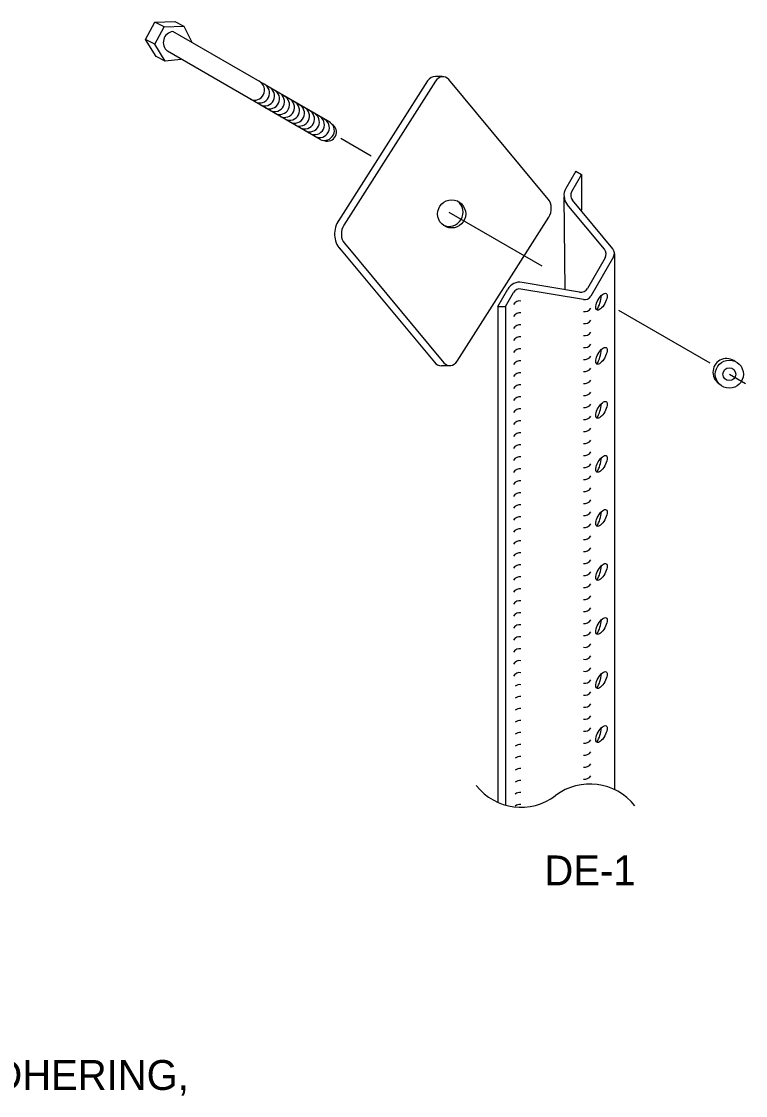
# Model space of a CAD drawing. Extents: x -0.14 to 2.7, y -0.05 to 1.78.
# Drawn here: x 0.3019 to 0.5037, y 1.2916 to 1.5909 of the extents above; entities that cross this region are included whole.
import ezdxf

# ---------------------------------------------------------------- set-up
doc = ezdxf.new("R2010")
doc.units = 0
doc.layers.add('CT_CSHT_GeneralLabel', color=7, linetype='Continuous')

msp = doc.modelspace()

# ---------------------------------------------------------------- linework, layer by layer
at = {"layer": 'CT_CSHT_GeneralLabel'}
for p, q in [((0.3364926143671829, 1.585867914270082), (0.3390890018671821, 1.590740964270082)), ((0.3390890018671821, 1.590740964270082), (0.34461068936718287, 1.590921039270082)), ((0.3416651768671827, 1.5894363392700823), (0.3390890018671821, 1.590740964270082)), ((0.34461068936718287, 1.590921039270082), (0.3471850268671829, 1.5896164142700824)), ((0.38788748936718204, 1.5628238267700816), (0.34410170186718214, 1.5881115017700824)), ((0.33940321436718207, 1.581174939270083), (0.3364926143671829, 1.585867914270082)), ((0.33906327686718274, 1.5845632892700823), (0.3364926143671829, 1.585867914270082)), ((0.34197755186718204, 1.5798721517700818), (0.33940321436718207, 1.581174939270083)), ((0.3851294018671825, 1.5580481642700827), (0.3425655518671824, 1.582633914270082)), ((0.4191782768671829, 1.575577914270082), (0.4173242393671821, 1.5756091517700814)), ((0.44870873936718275, 1.5414187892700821), (0.42096616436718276, 1.5747198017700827)), ((0.415060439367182, 1.574332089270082), (0.39022662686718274, 1.5353642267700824)), ((0.4172801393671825, 1.5742530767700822), (0.3917425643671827, 1.534177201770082)), ((0.3909303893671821, 1.5584028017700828), (0.3993975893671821, 1.5535150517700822)), ((0.4563747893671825, 1.549162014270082), (0.4536056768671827, 1.5443624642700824)), ((0.45799730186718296, 1.5482267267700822), (0.4552281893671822, 1.5434253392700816)), ((0.4563747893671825, 1.549162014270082), (0.45799730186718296, 1.5482267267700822)), ((0.45799730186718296, 1.5482267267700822), (0.45799730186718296, 1.5383464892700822)), ((0.4534347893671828, 1.5161568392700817), (0.4531095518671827, 1.542030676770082)), ((0.4643440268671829, 1.5274427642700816), (0.45397685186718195, 1.5399506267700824)), ((0.46667765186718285, 1.527565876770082), (0.45542112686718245, 1.5411468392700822)), ((0.4210378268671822, 1.5377327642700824), (0.4468932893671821, 1.5227994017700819)), ((0.4233291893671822, 1.4962732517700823), (0.448863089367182, 1.5363491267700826)), ((0.3905224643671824, 1.5276926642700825), (0.4169787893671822, 1.4959425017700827)), ((0.3918969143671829, 1.5291020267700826), (0.419646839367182, 1.495806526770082)), ((0.4645498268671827, 1.525013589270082), (0.45964370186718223, 1.5165114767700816)), ((0.4668687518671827, 1.5252818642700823), (0.4605679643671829, 1.5143652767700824)), ((0.4671351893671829, 1.5261712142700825), (0.4671351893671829, 1.3768578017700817)), ((0.4574350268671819, 1.515476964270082), (0.4414175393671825, 1.518198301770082)), ((0.434635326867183, 1.5115208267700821), (0.4374026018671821, 1.5163075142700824)), ((0.43680541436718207, 1.5115208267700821), (0.4390324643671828, 1.5153777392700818)), ((0.4584971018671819, 1.5133950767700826), (0.44110516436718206, 1.516351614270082)), ((0.434635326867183, 1.5115208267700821), (0.43680541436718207, 1.5115208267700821)), ((0.434635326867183, 1.5115208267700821), (0.434635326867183, 1.3733004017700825)), ((0.43680541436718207, 1.5115208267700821), (0.43680541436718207, 1.3725139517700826)), ((0.49380466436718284, 1.495712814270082), (0.46839387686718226, 1.5103870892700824)), ((0.4212601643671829, 1.4949429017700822), (0.4189173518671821, 1.4949833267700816)), ((0.49918302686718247, 1.4926092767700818), (0.5036812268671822, 1.4900110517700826))]:
    msp.add_line(p, q, dxfattribs=at)
msp.add_lwpolyline([(0.34627913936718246, 1.5803352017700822), (0.34197755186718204, 1.5798721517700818), (0.33906327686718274, 1.5845632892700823), (0.3416651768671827, 1.5894363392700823), (0.3471850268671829, 1.5896164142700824), (0.34942861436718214, 1.5851182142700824)], dxfattribs=at)
for centre, radius in [((0.42178613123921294, 1.5372863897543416), 0.003915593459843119), ((0.4991752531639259, 1.4926126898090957), 0.003920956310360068), ((0.499175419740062, 1.4926127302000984), 0.0017902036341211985)]:
    msp.add_circle(centre, radius, dxfattribs=at)
for centre, radius, start, end in [((0.34448246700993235, 1.5850742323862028), 0.0030591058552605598, 97.12240555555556, 231.71895833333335), ((0.3668943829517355, 1.5717612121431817), 0.002762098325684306, 243.87999722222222, 63.8798361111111), ((0.36828376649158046, 1.5709590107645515), 0.002762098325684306, 243.87999722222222, 63.8798361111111), ((0.3696731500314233, 1.5701568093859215), 0.002762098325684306, 243.87999722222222, 63.8798361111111), ((0.3710625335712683, 1.5693546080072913), 0.002762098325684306, 243.87999722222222, 63.8798361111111), ((0.3724519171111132, 1.5685524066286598), 0.002762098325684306, 243.87999722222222, 63.8798361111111), ((0.3738413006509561, 1.5677502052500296), 0.002762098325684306, 243.87999722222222, 63.8798361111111), ((0.375230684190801, 1.5669480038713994), 0.002762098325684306, 243.87999722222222, 63.8798361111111), ((0.3766200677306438, 1.5661458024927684), 0.002762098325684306, 243.87999722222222, 63.8798361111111), ((0.3780094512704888, 1.5653436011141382), 0.002762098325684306, 243.87999722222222, 63.8798361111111), ((0.37939883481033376, 1.564541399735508), 0.002762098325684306, 243.87999722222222, 63.8798361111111), ((0.3807882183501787, 1.5637391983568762), 0.002762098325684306, 243.87999722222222, 63.8798361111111), ((0.3821776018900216, 1.5629369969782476), 0.002762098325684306, 243.87999722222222, 63.8798361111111), ((0.3835669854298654, 1.562134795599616), 0.002762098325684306, 243.87999722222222, 63.8798361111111), ((0.3849563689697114, 1.5613325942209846), 0.002762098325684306, 243.87999722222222, 63.8798361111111), ((0.3863457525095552, 1.5605303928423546), 0.002762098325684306, 243.87999722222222, 63.8798361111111), ((0.3871676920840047, 1.560097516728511), 0.0025320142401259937, 249.07159166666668, 57.900780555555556), ((0.4569651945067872, 1.5424254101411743), 0.0038779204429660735, 149.99999444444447, 219.57910000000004), ((0.4569651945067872, 1.5424254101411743), 0.0020051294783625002, 149.99999444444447, 219.57910000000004), ((0.4210378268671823, 1.5377327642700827), 0.003915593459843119, 245.57146877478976, 52.79514068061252), ((0.4627001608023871, 1.5260794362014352), 0.002137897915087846, 330, 39.646766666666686), ((0.4651338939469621, 1.5262845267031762), 0.0020051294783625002, 330.0000027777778, 39.685836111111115), ((0.4407708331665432, 1.5143619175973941), 0.003891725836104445, 80.42088888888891, 149.99999444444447), ((0.44077026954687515, 1.5143749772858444), 0.0020051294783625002, 80.42088888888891, 149.99999444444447), ((0.4577943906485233, 1.5175823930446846), 0.0021374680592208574, 260.33658611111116, 329.9999916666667), ((0.44077026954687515, 1.5110330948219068), 0.0020051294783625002, 80.42088888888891, 149.99999444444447), ((0.4588330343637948, 1.515371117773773), 0.0020051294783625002, 260.31415833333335, 329.9999916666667), ((0.4545634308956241, 1.5152731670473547), 0.009025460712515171, 328.10828055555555, 355.1480833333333), ((0.44077026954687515, 1.5076912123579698), 0.0020051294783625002, 80.42088888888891, 149.99999444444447), ((0.4588330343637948, 1.5120292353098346), 0.0020051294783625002, 260.31415833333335, 329.9999916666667), ((0.44077026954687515, 1.5043493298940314), 0.0020051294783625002, 80.42088888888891, 149.99999444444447), ((0.4588330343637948, 1.5086873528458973), 0.0020051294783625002, 260.31415833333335, 329.9999916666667), ((0.44077026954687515, 1.5010074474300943), 0.0020051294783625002, 80.42088888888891, 149.99999444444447), ((0.4588330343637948, 1.5053454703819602), 0.0020051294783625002, 260.31415833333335, 329.9999916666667), ((0.4588330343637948, 1.5020035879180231), 0.0020051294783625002, 260.31415833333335, 329.9999916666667), ((0.44077026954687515, 1.497665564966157), 0.0020051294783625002, 80.42088888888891, 149.99999444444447), ((0.4588330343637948, 1.4986617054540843), 0.0020051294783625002, 260.31415833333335, 329.9999916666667), ((0.4545634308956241, 1.5002106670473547), 0.009025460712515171, 328.10828055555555, 355.1480833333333), ((0.4983980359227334, 1.4931787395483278), 0.0038036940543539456, 49.63861111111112, 235.0894777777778), ((0.44077026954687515, 1.4943236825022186), 0.0020051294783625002, 80.42088888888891, 149.99999444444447), ((0.4588330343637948, 1.4953198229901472), 0.0020051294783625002, 260.31415833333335, 329.9999916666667), ((0.44077026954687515, 1.4909818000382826), 0.0020051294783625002, 80.42088888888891, 149.99999444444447), ((0.4588330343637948, 1.49197794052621), 0.0020051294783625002, 260.31415833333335, 329.9999916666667), ((0.44077026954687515, 1.4876399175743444), 0.0020051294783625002, 80.42088888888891, 149.99999444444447), ((0.44077026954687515, 1.4842980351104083), 0.0020051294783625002, 80.42088888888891, 149.99999444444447), ((0.4588330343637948, 1.4886360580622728), 0.0020051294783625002, 260.31415833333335, 329.9999916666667), ((0.44077026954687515, 1.4809561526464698), 0.0020051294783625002, 80.42088888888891, 149.99999444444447), ((0.4588330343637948, 1.4852941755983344), 0.0020051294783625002, 260.31415833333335, 329.9999916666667), ((0.4545634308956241, 1.485148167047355), 0.009025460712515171, 328.10828055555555, 355.1480833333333), ((0.44077026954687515, 1.4776142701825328), 0.0020051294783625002, 80.42088888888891, 149.99999444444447), ((0.4588330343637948, 1.4819522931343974), 0.0020051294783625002, 260.31415833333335, 329.9999916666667), ((0.44077026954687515, 1.4742723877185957), 0.0020051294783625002, 80.42088888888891, 149.99999444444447), ((0.4588330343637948, 1.47861041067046), 0.0020051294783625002, 260.31415833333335, 329.9999916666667), ((0.44077026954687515, 1.4709305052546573), 0.0020051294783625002, 80.42088888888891, 149.99999444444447), ((0.4588330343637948, 1.4752685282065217), 0.0020051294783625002, 260.31415833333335, 329.9999916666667), ((0.4588330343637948, 1.4719266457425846), 0.0020051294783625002, 260.31415833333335, 329.9999916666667), ((0.44077026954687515, 1.46758862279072), 0.0020051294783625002, 80.42088888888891, 149.99999444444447), ((0.4588330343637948, 1.4685847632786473), 0.0020051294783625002, 260.31415833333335, 329.9999916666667), ((0.4545634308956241, 1.4700856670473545), 0.009025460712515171, 328.10828055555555, 355.1480833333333), ((0.44077026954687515, 1.464246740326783), 0.0020051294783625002, 80.42088888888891, 149.99999444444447), ((0.4588330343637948, 1.4652428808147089), 0.0020051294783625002, 260.31415833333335, 329.9999916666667), ((0.44077026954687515, 1.460904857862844), 0.0020051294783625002, 80.42088888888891, 149.99999444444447), ((0.44077026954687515, 1.457562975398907), 0.0020051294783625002, 80.42088888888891, 149.99999444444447), ((0.4588330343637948, 1.461900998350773), 0.0020051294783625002, 260.31415833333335, 329.9999916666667), ((0.44077026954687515, 1.45422109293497), 0.0020051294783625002, 80.42088888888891, 149.99999444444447), ((0.4588330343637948, 1.4585591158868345), 0.0020051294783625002, 260.31415833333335, 329.9999916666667), ((0.44077026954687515, 1.4508792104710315), 0.0020051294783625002, 80.42088888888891, 149.99999444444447), ((0.4588330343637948, 1.4552172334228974), 0.0020051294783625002, 260.31415833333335, 329.9999916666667), ((0.4545634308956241, 1.4550231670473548), 0.009025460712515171, 328.10828055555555, 355.1480833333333), ((0.44077026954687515, 1.4475373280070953), 0.0020051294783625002, 80.42088888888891, 149.99999444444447), ((0.4588330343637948, 1.4518753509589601), 0.0020051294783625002, 260.31415833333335, 329.9999916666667), ((0.44077026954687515, 1.444195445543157), 0.0020051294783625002, 80.42088888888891, 149.99999444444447), ((0.4588330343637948, 1.448533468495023), 0.0020051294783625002, 260.31415833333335, 329.9999916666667), ((0.4588330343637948, 1.4451915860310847), 0.0020051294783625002, 260.31415833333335, 329.9999916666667), ((0.44077026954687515, 1.4408535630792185), 0.0020051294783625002, 80.42088888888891, 149.99999444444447), ((0.4588330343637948, 1.4418497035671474), 0.0020051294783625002, 260.31415833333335, 329.9999916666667), ((0.44077026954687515, 1.4375116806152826), 0.0020051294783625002, 80.42088888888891, 149.99999444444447), ((0.4588330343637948, 1.4385078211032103), 0.0020051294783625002, 260.31415833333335, 329.9999916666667), ((0.4545634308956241, 1.4399606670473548), 0.009025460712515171, 328.10828055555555, 355.1480833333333), ((0.44077026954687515, 1.4341697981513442), 0.0020051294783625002, 80.42088888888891, 149.99999444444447), ((0.4588330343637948, 1.4351659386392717), 0.0020051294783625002, 260.31415833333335, 329.9999916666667), ((0.44077026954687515, 1.430827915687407), 0.0020051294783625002, 80.42088888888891, 149.99999444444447), ((0.44077026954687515, 1.42748603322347), 0.0020051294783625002, 80.42088888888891, 149.99999444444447), ((0.4588330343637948, 1.4318240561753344), 0.0020051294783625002, 260.31415833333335, 329.9999916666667), ((0.44077026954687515, 1.4241441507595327), 0.0020051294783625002, 80.42088888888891, 149.99999444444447), ((0.4588330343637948, 1.428482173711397), 0.0020051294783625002, 260.31415833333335, 329.9999916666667), ((0.44077026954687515, 1.4208022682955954), 0.0020051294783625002, 80.42088888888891, 149.99999444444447), ((0.4588330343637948, 1.42514029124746), 0.0020051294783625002, 260.31415833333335, 329.9999916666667), ((0.4545634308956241, 1.4248981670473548), 0.009025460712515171, 328.10828055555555, 355.1480833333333), ((0.44077026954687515, 1.417460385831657), 0.0020051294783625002, 80.42088888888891, 149.99999444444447), ((0.4588330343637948, 1.4217984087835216), 0.0020051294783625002, 260.31415833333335, 329.9999916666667), ((0.44077026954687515, 1.41411850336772), 0.0020051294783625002, 80.42088888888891, 149.99999444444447), ((0.4588330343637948, 1.4184565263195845), 0.0020051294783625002, 260.31415833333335, 329.9999916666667), ((0.4588330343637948, 1.4151146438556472), 0.0020051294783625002, 260.31415833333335, 329.9999916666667), ((0.44077026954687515, 1.4107766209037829), 0.0020051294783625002, 80.42088888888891, 149.99999444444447), ((0.4588330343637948, 1.4117727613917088), 0.0020051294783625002, 260.31415833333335, 329.9999916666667), ((0.44077026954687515, 1.4074347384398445), 0.0020051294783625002, 80.42088888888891, 149.99999444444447), ((0.4588330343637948, 1.4084308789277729), 0.0020051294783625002, 260.31415833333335, 329.9999916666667), ((0.4545634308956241, 1.409835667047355), 0.009025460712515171, 328.10828055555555, 355.1480833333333), ((0.44077026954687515, 1.4040928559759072), 0.0020051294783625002, 80.42088888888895, 130.60729166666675), ((0.4588330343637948, 1.4050889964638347), 0.0020051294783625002, 260.31415833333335, 329.9999916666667), ((0.44077026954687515, 1.40075097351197), 0.0020051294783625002, 80.42088888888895, 130.60729166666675), ((0.44077026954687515, 1.3974090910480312), 0.0020051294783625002, 80.42088888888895, 130.60729166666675), ((0.4588330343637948, 1.4017471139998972), 0.0020051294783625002, 260.31415833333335, 329.9999916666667), ((0.44077026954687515, 1.3940672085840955), 0.0020051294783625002, 80.42088888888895, 130.60729166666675), ((0.4588330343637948, 1.39840523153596), 0.0020051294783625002, 260.31415833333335, 329.9999916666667), ((0.44077026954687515, 1.390725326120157), 0.0020051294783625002, 80.42088888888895, 130.60729166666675), ((0.4588330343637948, 1.395063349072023), 0.0020051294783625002, 260.31415833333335, 329.9999916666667), ((0.4545634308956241, 1.3947731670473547), 0.009025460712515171, 328.10828055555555, 355.1480833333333), ((0.44077026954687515, 1.3873834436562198), 0.0020051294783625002, 80.42088888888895, 130.60729166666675), ((0.4588330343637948, 1.3917214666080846), 0.0020051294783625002, 260.31415833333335, 329.9999916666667), ((0.4588330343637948, 1.3883795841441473), 0.0020051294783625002, 260.31415833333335, 329.9999916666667), ((0.44077026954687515, 1.3840415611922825), 0.0020051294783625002, 80.42088888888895, 130.60729166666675), ((0.4588330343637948, 1.3850377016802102), 0.0020051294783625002, 260.31415833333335, 329.9999916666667), ((0.44077026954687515, 1.3806996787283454), 0.0020051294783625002, 80.42088888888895, 130.60729166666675), ((0.4588330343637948, 1.3816958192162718), 0.0020051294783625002, 260.31415833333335, 329.9999916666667), ((0.4411270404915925, 1.3877970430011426), 0.015882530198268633, 218.15082500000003, 307.21875833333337), ((0.44077026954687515, 1.377357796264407), 0.0020051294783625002, 80.42088888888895, 130.60729166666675), ((0.46034045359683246, 1.3625015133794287), 0.015882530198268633, 38.150825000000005, 127.21875833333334), ((0.44077026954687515, 1.3740159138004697), 0.0020051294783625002, 80.42088888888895, 130.60729166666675), ((0.44077026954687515, 1.3706740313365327), 0.0020051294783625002, 80.42088888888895, 130.60729166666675)]:
    msp.add_arc(centre, radius, start, end, dxfattribs=at)
for centre, major_axis, ratio, start_param, end_param in [((0.4172688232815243, 1.5726041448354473), (5.24916477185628e-05, 0.0030072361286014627), 0.899999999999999, 6.283185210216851, 7.256403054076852), ((0.4191980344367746, 1.5719496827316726), (0.0002746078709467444, 0.003596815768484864), 0.7207785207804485, 5.644935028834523, 7.215605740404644), ((0.4469452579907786, 1.5386493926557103), (0.00027460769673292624, 0.0035968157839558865), 0.720778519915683, 4.074012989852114, 5.644575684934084), ((0.393663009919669, 1.5318758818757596), (0.00037701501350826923, 0.005684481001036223), 0.7867206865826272, 0.9220534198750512, 2.492942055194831), ((0.393663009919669, 1.5318758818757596), (0.00027460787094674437, 0.003596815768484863), 0.7207785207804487, 0.9324204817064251, 2.503309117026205), ((0.4189696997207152, 1.4979885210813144), (-5.2491939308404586e-05, -0.0030072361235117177), 0.8999999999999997, 5.476378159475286, 6.283185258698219), ((0.4214104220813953, 1.4985752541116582), (-0.0002746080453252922, -0.0035968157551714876), 0.720778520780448, 5.644631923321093, 7.215486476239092)]:
    msp.add_ellipse(centre, major_axis=major_axis, ratio=ratio, start_param=start_param, end_param=end_param, dxfattribs=at)
for centre in [(0.4635284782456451, 1.512799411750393), (0.4635284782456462, 1.497736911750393), (0.4635284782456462, 1.482674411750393), (0.4635284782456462, 1.4676119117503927), (0.4635284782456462, 1.4525494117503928), (0.4635284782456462, 1.4374869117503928), (0.4635284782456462, 1.422424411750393), (0.4635284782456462, 1.407361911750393), (0.4635284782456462, 1.3922994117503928)]:
    msp.add_ellipse(centre, major_axis=(0.00130166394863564, 0.002294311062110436), ratio=0.40310763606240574, dxfattribs=at)

# ---------------------------------------------------------------- texts
for s, p in [('DE-1', (0.4476386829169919, 1.3501318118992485)), ('FACE SHALL BE PRESSURE SENSITIVE, SELF ADHERING, ', (0.037689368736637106, 1.2931060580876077))]:
    msp.add_text(s, height=0.008333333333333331, dxfattribs=at).set_placement(p)

doc.saveas('drawing.dxf')
